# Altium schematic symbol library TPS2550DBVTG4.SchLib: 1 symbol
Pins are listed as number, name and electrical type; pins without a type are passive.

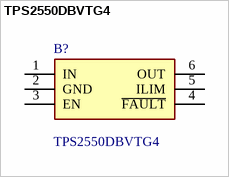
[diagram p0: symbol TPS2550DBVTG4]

## TPS2550DBVTG4
designator B?
USB Power SW Hi Side/DIST Single 6.5V 0.1A to 1.1A 6-Pin SOT-23 T/R; Manufacturer_Name: Texas Instruments; Geometry.Height: 1.45mm
footprint SOT95P280X145-6N
pins: 1 IN, 2 GND, 3 EN, 4 ~{FAULT}, 5 ILIM, 6 OUT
